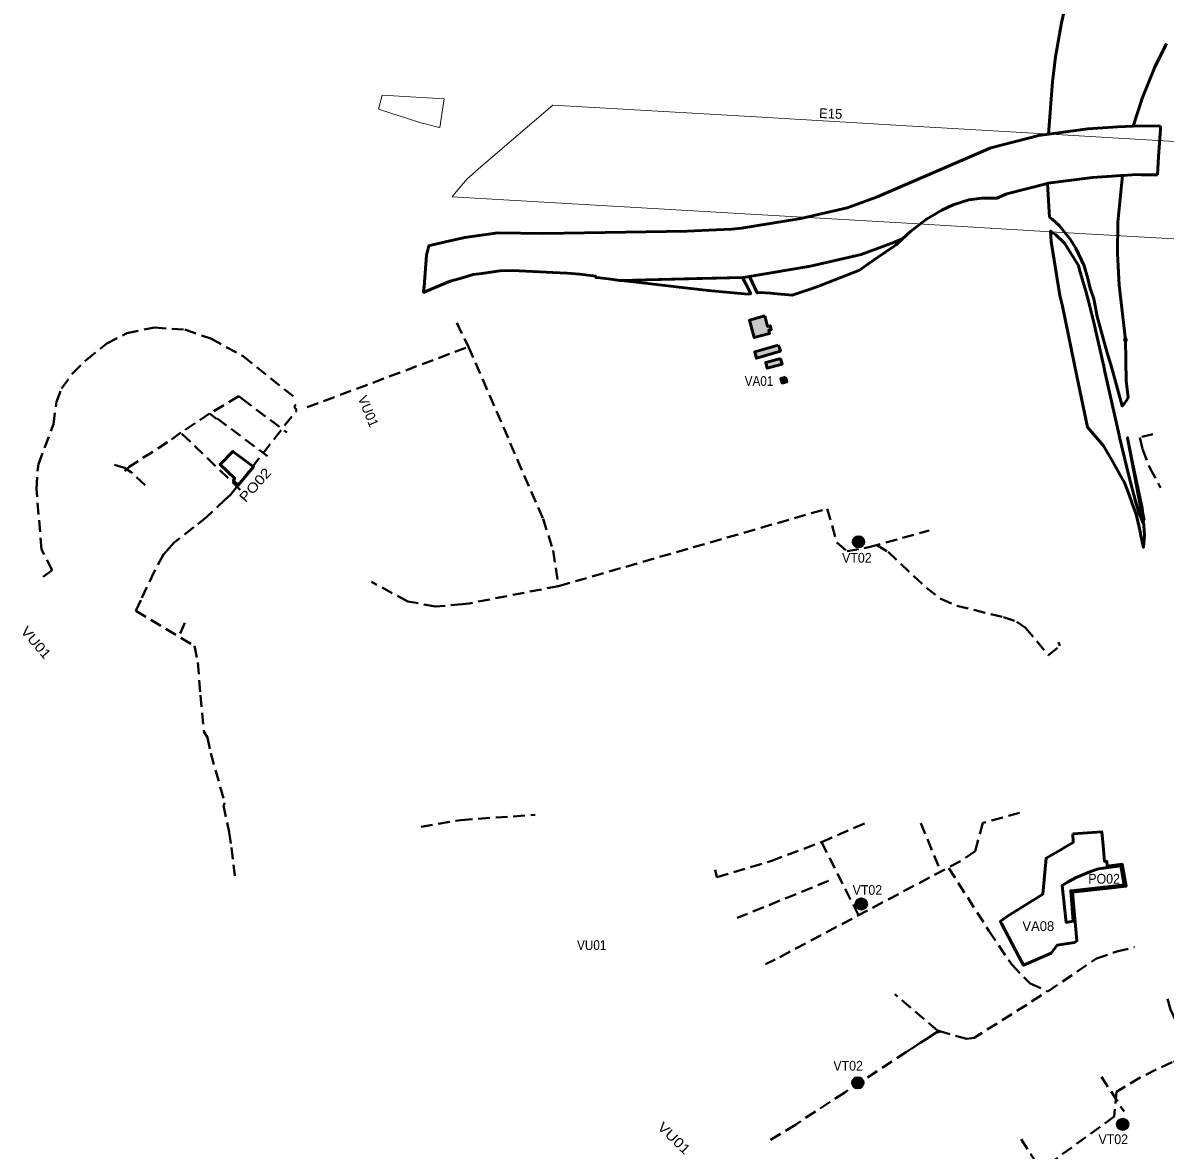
# Model space of a CAD drawing. Extents: x -650145 to -642675, y -1074338 to -1066803.
# Drawn here: x -650145 to -647799, y -1071056 to -1068740 of the extents above; entities that cross this region are included whole.
import ezdxf

# ---------------------------------------------------------------- set-up
doc = ezdxf.new("R2010")
doc.units = 0
doc.header["$LTSCALE"] = 8
doc.header["$PDMODE"] = 32
doc.header["$PDSIZE"] = 4
doc.linetypes.add('MEDIUM_DASHED', pattern=[4.5, 3, -1.5])
for name, color, linetype, lineweight in [('12', 7, 'MEDIUM_DASHED', 40), ('13', 7, 'MEDIUM_DASHED', 40), ('15', 7, 'Continuous', 13), ('20', 7, 'Continuous', 13), ('44', 7, 'Continuous', 53), ('45', 7, 'Continuous', 53), ('46', 7, 'Continuous', 53), ('54', 7, 'Continuous', 53), ('60', 7, 'Continuous', 53)]:
    doc.layers.add(name, color=color, linetype=linetype, lineweight=lineweight)
for name, color, linetype in [('17', 7, 'Continuous'), ('2', 7, 'Continuous'), ('3', 7, 'Continuous'), ('5', 7, 'Continuous'), ('6', 7, 'Continuous')]:
    doc.layers.add(name, color=color, linetype=linetype)

msp = doc.modelspace()

# ---------------------------------------------------------------- hatches: boundary and pattern name
at = {"layer": '15'}
for points in [[(-648416.978, -1069806.101, 1), (-648440.503, -1069806.101, 1)], [(-648411.342, -1070550.264, 1), (-648434.867, -1070550.264, 1)], [(-648418.374, -1070917.603, 1), (-648441.898, -1070917.603, 1)], [(-647874.426, -1071003.073, 1), (-647897.951, -1071003.073, 1)]]:
    msp.add_hatch(color=256, dxfattribs=at).paths.add_polyline_path(points)
at = {"layer": '60'}
for points in [[(-648621.37, -1069342.03), (-648652.93, -1069350.8), (-648642.85, -1069386.53), (-648611.53, -1069377.7), (-648613.3, -1069371.42), (-648608.07, -1069369.95), (-648610.3, -1069362.04), (-648615.51, -1069363.51)], [(-648593.77, -1069401.82), (-648642.06, -1069415.98), (-648638.41, -1069428.97), (-648589.26, -1069414.15), (-648592.11, -1069405.18)], [(-648589.16, -1069429.3), (-648619.35, -1069437.29), (-648616.15, -1069449.33), (-648585.96, -1069441.33)], [(-648578.5, -1069467.6), (-648588.59, -1069470.49), (-648585.91, -1069479.97), (-648575.76, -1069477.15)]]:
    msp.add_hatch(color=256, dxfattribs=at).paths.add_polyline_path(points)

# ---------------------------------------------------------------- linework, layer by layer
at = {"layer": '12'}
for p, q in [((-649561.229, -1069529.679), (-649230.09, -1069405.382)), ((-649812.401, -1069972.556), (-649825.281, -1070000.693)), ((-648300.887, -1070383.875), (-648259.756, -1070483.608)), ((-648504.855, -1070423.103), (-648428.725, -1070573.36)), ((-648490.212, -1070502.827), (-648678.059, -1070578.955)), ((-648332.818, -1070855.794), (-648263.929, -1070810.849)), ((-647929.7, -1070905.7), (-647883.483, -1070976.724)), ((-648042.555, -1071114.098), (-648099.428, -1071026.867))]:
    msp.add_line(p, q, dxfattribs=at)
for points in [[(-649253.852, -1069356.119), (-649230.09, -1069405.382), (-649076.593, -1069758.743), (-649056.232, -1069823.932), (-649044.908, -1069897.057), (-649228.331, -1069932.561), (-649242.081, -1069934.228), (-649297.984, -1069939.047), (-649354.851, -1069928.445), (-649429.2, -1069888.2)], [(-650103.474, -1069877.787), (-650084.938, -1069864.261), (-650106.91, -1069821.516), (-650117.539, -1069697.081), (-650115.437, -1069660.575), (-650113.146, -1069646.371), (-650082.659, -1069564.521), (-650076.339, -1069518.627), (-650065.774, -1069491.142), (-650043.673, -1069460), (-650014.541, -1069431.96), (-649972.852, -1069398.452), (-649931.689, -1069377.161), (-649874.912, -1069365.805), (-649812.457, -1069370.063), (-649759.229, -1069388.516), (-649693.075, -1069424.839), (-649582.474, -1069512.785)], [(-647823.978, -1069584.663), (-647851.235, -1069591.7), (-647845.629, -1069616.01), (-647830.41, -1069654.06), (-647808.595, -1069694.89)], [(-649894.276, -1069689.929), (-649922.552, -1069662.785), (-649936.52, -1069654.039), (-649956.998, -1069647.787)], [(-649729.723, -1069719.048), (-649767.23, -1069754.779), (-649794.247, -1069776.092), (-649834.299, -1069807.359), (-649851.029, -1069825.755), (-649856.254, -1069832.159), (-649875.133, -1069866.696), (-649903.303, -1069925.944), (-649913.581, -1069947.56), (-649793.063, -1070020.079), (-649786.071, -1070054.229), (-649780.314, -1070121.295), (-649773.322, -1070195.767), (-649766.003, -1070207.927), (-649759.422, -1070240.431), (-649730.633, -1070342.059), (-649733.512, -1070347.819), (-649721.595, -1070402.368), (-649717.071, -1070434.049), (-649709.95, -1070492.08)], [(-649044.908, -1069897.057), (-648493.206, -1069738.027), (-648473.126, -1069807.804), (-648452.457, -1069825.52), (-648407.58, -1069817.388), (-648283.564, -1069782.827)], [(-648391.301, -1069812.851), (-648368.286, -1069826.694), (-648289.499, -1069900.443), (-648259.719, -1069923.17), (-648226.806, -1069937.698), (-648130.85, -1069960.81), (-648103.867, -1069970.198), (-648085.696, -1069982.585), (-648038.819, -1070039.248), (-648015.643, -1070020.009), (-648018.277, -1070012.103)], [(-649327.442, -1070392.02), (-649245.779, -1070377.706), (-649092.777, -1070367.093)], [(-648097.961, -1070362.859), (-648173.666, -1070383.828), (-648189.212, -1070442.001), (-648219.63, -1070462.294), (-648600.13, -1070664.406), (-648620.205, -1070674.13)], [(-648723.27, -1070480.1), (-648719.781, -1070495.186), (-648608.642, -1070462.104), (-648504.855, -1070423.103), (-648414.278, -1070383.546)], [(-648243.287, -1070476.499), (-648161.107, -1070605.619), (-648114.121, -1070674.786), (-648076.532, -1070713.851), (-648039.863, -1070730.017), (-647940.305, -1070662.397), (-647898.38, -1070648.071), (-647862.25, -1070638.96)], [(-648053, -1070737.9), (-648191.415, -1070825.487), (-648206.369, -1070827.623), (-648259.779, -1070812.134), (-648269.723, -1070814.735), (-648457.192, -1070937.393), (-648558.532, -1071003.71), (-648610.798, -1071035.598)], [(-648259.67, -1070812.106), (-648266.577, -1070810.067), (-648354.282, -1070735.576)], [(-647794.16, -1070745.19), (-647787.83, -1070767.157), (-647743.987, -1070862.016), (-647758.284, -1070869.702), (-647784.836, -1070875.103), (-647850.393, -1070906.456), (-647898.698, -1070936.31), (-647903.521, -1070987.043), (-648287.54, -1071265.293)]]:
    msp.add_lwpolyline(points, dxfattribs=at)
at = {"layer": '13'}
for p, q in [((-649694.802, -1069512.123), (-649603.303, -1069581.446)), ((-649747.394, -1069553.384), (-649761.703, -1069542.629)), ((-649745.861, -1069552.374), (-649642.892, -1069630.01)), ((-649818.581, -1069583.853), (-649698.883, -1069699.094))]:
    msp.add_line(p, q, dxfattribs=at)
for points in [[(-649694.802, -1069512.123), (-649701.606, -1069507.025), (-649761.703, -1069542.629), (-649820.632, -1069581.735), (-649848.054, -1069601.58), (-649926.821, -1069651.776), (-649936.049, -1069660.598)], [(-649729.723, -1069719.048), (-649718.864, -1069709.812), (-649652.035, -1069623.949), (-649582.548, -1069535.427), (-649587.864, -1069528.968), (-649584.447, -1069523.65)]]:
    msp.add_lwpolyline(points, dxfattribs=at)
at = {"layer": '15', "lineweight": 35}
for centre in [(-648428.74, -1069806.101), (-648423.104, -1070550.264), (-648430.136, -1070917.603), (-647886.188, -1071003.073)]:
    msp.add_circle(centre, 11.762, dxfattribs=at)
at = {"layer": '20'}
for points in [[(-645696.222, -1068110.701), (-645999.704, -1068380.07), (-646264.963, -1068537.869), (-646558.558, -1068712.401), (-646840.473, -1068879.978), (-647082.853, -1069024.029), (-647392.269, -1069006.02), (-647721.495, -1068986.72), (-648010.52, -1068969.88), (-648329.902, -1068951.251), (-648639.277, -1068933.111), (-648948.071, -1068915.071), (-649057.05, -1068908.69), (-649199.47, -1069030.73), (-649232.77, -1069060.44), (-649258.79, -1069091.17), (-649263.719, -1069096.97)], [(-649263.719, -1069096.97), (-648650.963, -1069132.769), (-648341.578, -1069150.909), (-648022.16, -1069169.54), (-647733.165, -1069186.38), (-647403.931, -1069205.68), (-647033.327, -1069227.251), (-646738.287, -1069051.902)]]:
    msp.add_lwpolyline(points, dxfattribs=at)
msp.add_lwpolyline([(-649319.15, -1068947.37), (-649308.65, -1068950), (-649293.04, -1068953.81), (-649291.32, -1068954.23), (-649288.57, -1068954.9), (-649280.244, -1068895.622), (-649407.325, -1068888.181), (-649415.09, -1068917.1), (-649327.68, -1068945.23), (-649326.13, -1068945.72)], close=True, dxfattribs=at)
at = {"layer": '44'}
for p, q in [((-648038.596, -1068968.281), (-647958.168, -1068957.73)), ((-647862.266, -1069668.613), (-647843.449, -1069768.252))]:
    msp.add_line(p, q, dxfattribs=at)
for points in [[(-647801.797, -1068219.34), (-647843.6, -1068292.629), (-647868.214, -1068337.803), (-647914.339, -1068432.512), (-647946.187, -1068510.254), (-647971.074, -1068581.98), (-647997.27, -1068674.747), (-648011.775, -1068739.718), (-648023.914, -1068809.332), (-648030.73, -1068861.213), (-648038.596, -1068968.281)], [(-647846.989, -1068896.545), (-647820.883, -1068832.117), (-647797.632, -1068784.713), (-647796.173, -1068782.191)], [(-647958.168, -1068957.73), (-647895.901, -1068953.392), (-647864.531, -1068951.823), (-647847.197, -1068897.199), (-647847.034, -1068896.687), (-647846.989, -1068896.545)], [(-647886.615, -1069053.052), (-647889.927, -1069053.218), (-647948.18, -1069057.276)], [(-647893.553, -1069279.017), (-647896.67, -1069213.573), (-647896.362, -1069149.171), (-647886.615, -1069053.052)], [(-647948.18, -1069057.276), (-648039.666, -1069069.279), (-648040.705, -1069069.548), (-648036.291, -1069139.458)], [(-648036.291, -1069139.458), (-648031.92, -1069142.67), (-648016.36, -1069156.54), (-647993.8, -1069184.11)], [(-648005.47, -1069192.09), (-648024.02, -1069174.7), (-648034.421, -1069167.61)], [(-648034.421, -1069167.61), (-648034.421, -1069167.61), (-648033, -1069189), (-648015, -1069300), (-648010.092, -1069322.087), (-647980.331, -1069465.915), (-647958.34, -1069570.699), (-647925.99, -1069608.57), (-647906.16, -1069641.48), (-647885.665, -1069678.788), (-647885.663, -1069678.794), (-647883.51, -1069682.71), (-647875.82, -1069701.85), (-647875.82, -1069701.85), (-647864.19, -1069735.12), (-647858.44, -1069749.43), (-647852.63, -1069775.7), (-647850.66, -1069785.74), (-647849.165, -1069793.367)], [(-648354.978, -1069190.492), (-648423.173, -1069215.44), (-648527.693, -1069239.938), (-648652.716, -1069260.657), (-648647.059, -1069272.723), (-648636.85, -1069294.49), (-648630.82, -1069293.63), (-648609.425, -1069295.033), (-648603.228, -1069295.53), (-648565.18, -1069299.46), (-648526.15, -1069286.21)], [(-648526.15, -1069286.21), (-648508.95, -1069280.01), (-648427.08, -1069247.75), (-648407.73, -1069233.88), (-648389.91, -1069221.86), (-648355.81, -1069198.88), (-648351.77, -1069195.88), (-648338.523, -1069183.389), (-648354.978, -1069190.492)], [(-647962.2, -1069290.88), (-647974.81, -1069246.86), (-647977.29, -1069238.21), (-648005.47, -1069192.09)], [(-647993.8, -1069184.11), (-647982.58, -1069202.33), (-647965.06, -1069238.95), (-647957.56, -1069264.74), (-647953.01, -1069285.73), (-647951.841, -1069289.09)], [(-647852.78, -1069745.71), (-647859.722, -1069722.428), (-647872.87, -1069673.56), (-647892.79, -1069591.06), (-647892.789, -1069591.06), (-647893.75, -1069587.08), (-647922.04, -1069459.71), (-647925.16, -1069445.68), (-647928.41, -1069431.03), (-647945.28, -1069355.1), (-647956.27, -1069311.58), (-647962.2, -1069290.88)], [(-647951.841, -1069289.09), (-647945.63, -1069306.95), (-647938.77, -1069343.17), (-647918.08, -1069417.43), (-647909.67, -1069444.46), (-647889.22, -1069519.32), (-647887.087, -1069527.229), (-647885.782, -1069525.389), (-647882.551, -1069520.835), (-647878.73, -1069515.45)], [(-647880.318, -1069391.297), (-647880.326, -1069390.832), (-647893.553, -1069279.017)], [(-647878.73, -1069515.45), (-647874.75, -1069509.84), (-647878.93, -1069475.09), (-647880.318, -1069391.297)], [(-647843.449, -1069768.252), (-647844.371, -1069761.991), (-647842.438, -1069760.647), (-647845.086, -1069748.753), (-647846.484, -1069736.663), (-647855.158, -1069695.232), (-647865.69, -1069647.32), (-647876.061, -1069592.206), (-647862.266, -1069668.613)], [(-647841.402, -1069792.351), (-647842.489, -1069773.282), (-647842.622, -1069770.956), (-647843.337, -1069769.013), (-647843.443, -1069768.293), (-647852.78, -1069745.71)], [(-647849.165, -1069793.367), (-647843.74, -1069817.63), (-647841.402, -1069792.351)]]:
    msp.add_lwpolyline(points, dxfattribs=at)
msp.add_lwpolyline([(-648730.66, -1069290.43), (-648655.53, -1069297.18), (-648650.06, -1069296.39), (-648650.58, -1069295.34), (-648662.417, -1069271.858), (-648666.827, -1069262.738), (-648761.189, -1069265.035), (-648918.889, -1069268.875), (-648909.86, -1069270.02), (-648861.49, -1069275.34), (-648785.92, -1069284.2), (-648730.66, -1069290.43)], close=True, dxfattribs=at)
msp.add_arc((-648354.978, -1069190.492), 0.000000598, 264.13978, 298.69712, dxfattribs=at)
msp.add_point((-647880.318, -1069391.297), dxfattribs=at)
at = {"layer": '45'}
for points in [[(-647864.531, -1068951.823), (-647895.901, -1068953.392), (-647958.168, -1068957.73), (-648038.596, -1068968.281), (-648038.759, -1068968.54)], [(-647808.28, -1068952.066), (-647850.043, -1068951.098), (-647864.531, -1068951.823)], [(-647814.401, -1069052.246), (-647812.34, -1069014.54), (-647808.67, -1068958.06), (-647808.28, -1068952.066)], [(-648038.759, -1068968.54), (-648038.746, -1068968.301), (-648058.764, -1068970.927), (-648156.739, -1068996.273), (-648392.002, -1069097.554), (-648451.865, -1069119.456), (-648547.243, -1069141.81), (-648668.959, -1069161.838), (-648688.912, -1069163.603), (-648721.315, -1069164.952), (-648781.015, -1069167.44), (-649076.02, -1069172.683), (-649169.781, -1069171.432), (-649237.512, -1069180.731), (-649277.021, -1069189.913), (-649306.455, -1069196.754), (-649311.633, -1069197.958), (-649316.47, -1069216.91), (-649321.32, -1069281.47), (-649322.09, -1069291.73), (-649322.22, -1069293.54), (-649319.72, -1069292.47), (-649267.5, -1069270.41), (-649242.5, -1069263.3), (-649220.18, -1069257.03), (-649202.63, -1069254.4), (-649165.62, -1069249.43), (-649139.63, -1069248.73), (-649056.95, -1069252.55), (-649026.955, -1069254.366), (-649001.3, -1069255.92), (-648968.49, -1069260.36), (-648968.05, -1069263.06), (-648965.8, -1069262.75), (-648937.91, -1069266.51), (-648924.13, -1069268.21), (-648918.889, -1069268.875), (-648665.007, -1069262.694), (-648527.693, -1069239.938), (-648423.173, -1069215.44), (-648354.978, -1069190.492), (-648338.523, -1069183.389), (-648322.14, -1069168.56), (-648306.83, -1069156.57), (-648289.25, -1069142.79), (-648257.5, -1069124.41), (-648234.22, -1069113.6), (-648202.46, -1069103.3), (-648175.65, -1069099.64), (-648144.866, -1069099.987), (-648124.327, -1069091.181), (-648040.705, -1069069.547)], [(-648040.705, -1069069.547), (-648039.666, -1069069.279), (-647948.18, -1069057.276), (-647886.615, -1069053.052), (-647856.541, -1069051.548), (-647848.615, -1069051.679), (-647842.888, -1069051.774), (-647814.401, -1069052.246)]]:
    msp.add_lwpolyline(points, dxfattribs=at)
at = {"layer": '46'}
msp.add_lwpolyline([(-647883.383, -1070511.163), (-647889.978, -1070472.005), (-647936.144, -1070478.187), (-647950.48, -1070482.79), (-647962.184, -1070487.748), (-647981.81, -1070496.06), (-647999.756, -1070505.655), (-648010.831, -1070512.588), (-648002, -1070588), (-647987.667, -1070585.565), (-647992.819, -1070523.117)], close=True, dxfattribs=at)
at = {"layer": '54'}
msp.add_lwpolyline([(-649713.73, -1069620.32), (-649713.73, -1069620.32), (-649740.23, -1069647.14), (-649709.94, -1069676.28), (-649712.54, -1069678.98), (-649712.89, -1069679.87), (-649712.51, -1069680.75), (-649703.15, -1069689.75), (-649671.39, -1069651.93), (-649693.63, -1069635.33)], close=True, dxfattribs=at)
at = {"layer": '60'}
for points in [[(-648621.37, -1069342.03), (-648652.93, -1069350.8), (-648642.85, -1069386.53), (-648611.53, -1069377.7), (-648613.3, -1069371.42), (-648608.07, -1069369.95), (-648610.3, -1069362.04), (-648615.51, -1069363.51)], [(-648593.77, -1069401.82), (-648642.06, -1069415.98), (-648638.41, -1069428.97), (-648589.26, -1069414.15), (-648592.11, -1069405.18)], [(-648589.16, -1069429.3), (-648619.35, -1069437.29), (-648616.15, -1069449.33), (-648585.96, -1069441.33)], [(-648578.5, -1069467.6), (-648588.59, -1069470.49), (-648585.91, -1069479.97), (-648575.76, -1069477.15)], [(-647988.86, -1070405.95), (-647988.11, -1070423.93), (-648005.668, -1070434.145), (-648014.63, -1070439.36), (-648043.43, -1070456.12), (-648050.38, -1070530.2), (-648122.57, -1070575), (-648137.78, -1070586.25), (-648135.47, -1070590.61), (-648098.637, -1070659.682), (-648089.82, -1070676.22), (-648033.29, -1070651.18), (-648020.51, -1070635.05), (-647985.44, -1070629.07), (-647980.2, -1070625.7), (-647989.5, -1070525.73), (-647901.695, -1070516.259), (-647879.16, -1070513.83), (-647887.08, -1070468.54), (-647917.98, -1070472.47), (-647918.95, -1070462.36), (-647923.53, -1070462.75), (-647926.53, -1070429.76), (-647929.24, -1070401.97)]]:
    msp.add_lwpolyline(points, close=True, dxfattribs=at)

# ---------------------------------------------------------------- texts
at = {"layer": '17', "width": 0.95}
for p in [(-648462.628, -1069848.885), (-648441.04, -1070531.428), (-648480.548, -1070892.65), (-647935.934, -1071043.636)]:
    msp.add_text('VT02', height=20, dxfattribs=at).set_placement(p)
at = {"layer": '2'}
msp.add_text('VU01', height=20, rotation=292.277, dxfattribs=at).set_placement((-649457.739, -1069510.652))
for rotation, width, p in [(310.892, 1.15, (-650151.079, -1069990.662)), (315.876, 1.2, (-648843.543, -1071010.613))]:
    msp.add_text('VU01', height=20, rotation=rotation, dxfattribs=dict(at, width=width)).set_placement(p)
at = {"layer": '2', "width": 0.9}
msp.add_text('VU01', height=20, dxfattribs=at).set_placement((-649006.975, -1070644.798))
at = {"layer": '20'}
msp.add_text('E15', height=20, rotation=357.579, dxfattribs=at).set_placement((-648510.172, -1068935.14))
at = {"layer": '3', "width": 0.9}
msp.add_text('VA01', height=20, dxfattribs=at).set_placement((-648662.691, -1069485.662))
at = {"layer": '3'}
msp.add_text('VA08', height=20, dxfattribs=at).set_placement((-648092.311, -1070605.712))
at = {"layer": '5', "width": 0.95}
msp.add_text('PO02', height=20, dxfattribs=at).set_placement((-647956.859, -1070508.429))
at = {"layer": '6', "width": 1.2}
msp.add_text('PO02', height=20, rotation=48.242, dxfattribs=at).set_placement((-649688.011, -1069726.505))

doc.saveas('drawing.dxf')
